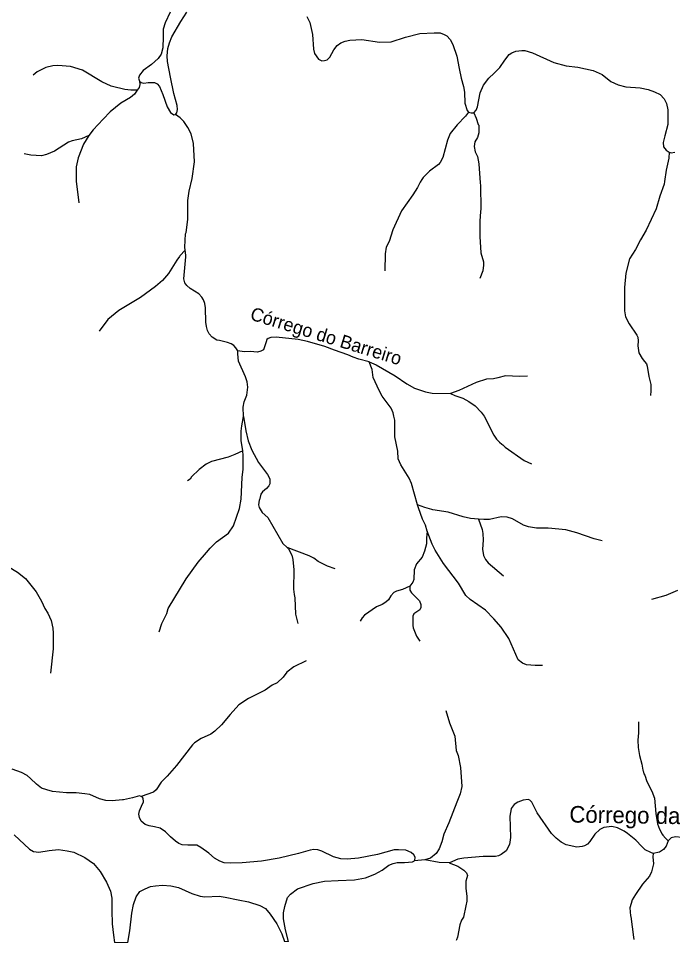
# Model space of a CAD drawing. Extents: x 396 to 422.2, y 7649.8 to 7677.6.
# Drawn here: x 405.17 to 409.11, y 7649.88 to 7655.45 of the extents above; entities that cross this region are included whole.
import ezdxf
from ezdxf.enums import TextEntityAlignment as Align

# ---------------------------------------------------------------- set-up
doc = ezdxf.new("R2010")
doc.units = 0
doc.header["$LTSCALE"] = 0.032
doc.linetypes.add('SHORT_DASHED', pattern=[2.7, 1.5, -1.2])
for name, color, linetype, lineweight in [('2', 7, 'Continuous', 25), ('62', 7, 'SHORT_DASHED', 13), ('7', 7, 'Continuous', 25)]:
    doc.layers.add(name, color=color, linetype=linetype, lineweight=lineweight)
doc.layers.add('61', color=7, linetype='Continuous')

msp = doc.modelspace()

# ---------------------------------------------------------------- linework, layer by layer
at = {"layer": '2'}
for points in [[(406.0836, 7655.4872), (406.0541, 7655.4214), (406.0423, 7655.384), (406.0423, 7655.3368), (406.0394, 7655.2719), (406.0305, 7655.2336), (406.0128, 7655.207), (405.9715, 7655.1716), (405.9223, 7655.1342), (405.8987, 7655.1067), (405.8938, 7655.088), (405.8995, 7655.0714)], [(406.1173, 7654.869), (406.1249, 7654.8796), (406.1288, 7654.8992), (406.1259, 7654.9238), (406.1072, 7654.9966), (406.0875, 7655.0949), (406.0679, 7655.1883), (406.0669, 7655.2227), (406.0708, 7655.268), (406.0797, 7655.3014), (406.0944, 7655.3368), (406.1485, 7655.4302), (406.1849, 7655.4853)], [(406.9086, 7655.4597), (406.9263, 7655.4233), (406.942, 7655.3525), (406.9489, 7655.2631), (406.9538, 7655.2375), (406.9794, 7655.2031), (406.9981, 7655.1932), (407.0158, 7655.1942), (407.0305, 7655.2001), (407.0462, 7655.2159), (407.0708, 7655.2601), (407.0905, 7655.2857), (407.1131, 7655.3024), (407.1387, 7655.3112), (407.1682, 7655.3181), (407.239, 7655.3211), (407.3462, 7655.3053), (407.416, 7655.3073), (407.5025, 7655.3348), (407.589, 7655.3575), (407.6756, 7655.3624), (407.7129, 7655.3624), (407.7365, 7655.3525), (407.7523, 7655.3437), (407.7719, 7655.3221), (407.7886, 7655.2906), (407.8122, 7655.2208), (407.827, 7655.147), (407.8378, 7655.089), (407.8526, 7655.0389), (407.8594, 7655.0054), (407.8614, 7654.9376), (407.8742, 7654.8933), (407.8833, 7654.8837)], [(407.9149, 7654.8798), (407.9292, 7654.8953), (407.9381, 7654.916), (407.946, 7654.9582), (407.9538, 7655.0005), (407.9735, 7655.0467), (408.0059, 7655.089), (408.0374, 7655.1185), (408.0708, 7655.1539), (408.1013, 7655.1972), (408.1289, 7655.2306), (408.1436, 7655.2414), (408.1692, 7655.2513), (408.2046, 7655.2562), (408.2223, 7655.2562), (408.2695, 7655.2404), (408.3983, 7655.1834), (408.471, 7655.1637), (408.5428, 7655.1559), (408.6343, 7655.1352), (408.6884, 7655.1116), (408.7415, 7655.0684), (408.7847, 7655.0477), (408.8309, 7655.0369), (408.9175, 7655.03), (408.9656, 7655.0212), (409.004, 7655.0074), (409.0374, 7654.9897), (409.062, 7654.9641), (409.0758, 7654.9366), (409.0836, 7654.8973), (409.0836, 7654.8688), (409.0846, 7654.8088), (409.0669, 7654.7419), (409.0561, 7654.7006), (409.0591, 7654.676), (409.0738, 7654.6554), (409.0918, 7654.6429)], [(405.8995, 7655.0714), (405.9096, 7655.0634), (405.9263, 7655.0585), (405.9528, 7655.0634), (405.9892, 7655.0634), (406.0059, 7655.0546), (406.0207, 7655.0389), (406.0394, 7654.9907), (406.0659, 7654.916), (406.0856, 7654.8825), (406.1072, 7654.8688), (406.1173, 7654.869)], [(407.8833, 7654.8837), (407.8988, 7654.8796), (407.9149, 7654.8798)], [(409.0918, 7654.6429), (409.1053, 7654.6387), (409.1259, 7654.6426)], [(405.9096, 7650.7626), (405.8999, 7650.7654), (405.8568, 7650.7537), (405.8033, 7650.7421), (405.7966, 7650.7415), (405.7346, 7650.7363), (405.6974, 7650.7386), (405.6589, 7650.7491), (405.5996, 7650.7747), (405.5705, 7650.7793), (405.5181, 7650.784), (405.4588, 7650.784), (405.3761, 7650.7921), (405.3412, 7650.8026), (405.3086, 7650.8131), (405.2783, 7650.8364), (405.2423, 7650.8713), (405.2225, 7650.8887), (405.1876, 7650.9074), (405.1329, 7650.9271)], [(407.5579, 7650.3752), (407.562, 7650.3906), (407.5608, 7650.3976), (407.5527, 7650.4115), (407.5375, 7650.4243), (407.5049, 7650.4383), (407.4607, 7650.4418), (407.4339, 7650.4418), (407.3338, 7650.4138), (407.2198, 7650.3906), (407.1523, 7650.3848), (407.1127, 7650.3871), (407.0696, 7650.3987), (406.9986, 7650.4336), (406.9753, 7650.4418), (406.9509, 7650.4429), (406.9288, 7650.4395), (406.8578, 7650.4197), (406.7414, 7650.3917), (406.6343, 7650.3731), (406.5191, 7650.3638), (406.4458, 7650.3615), (406.4097, 7650.3638), (406.3841, 7650.3731), (406.3526, 7650.3917), (406.3177, 7650.4208), (406.27, 7650.4558), (406.2456, 7650.4686), (406.2235, 7650.4697), (406.1909, 7650.4697), (406.1559, 7650.472), (406.1373, 7650.479), (406.1164, 7650.493), (406.0873, 7650.5198), (406.0558, 7650.55), (406.0233, 7650.5721), (405.9907, 7650.5791), (405.9581, 7650.5861), (405.9336, 7650.5943), (405.9104, 7650.614), (405.8987, 7650.635), (405.8964, 7650.6559), (405.8987, 7650.6769), (405.9127, 7650.7048), (405.9232, 7650.7293), (405.922, 7650.7514), (405.9162, 7650.7607), (405.9096, 7650.7626)], [(405.1437, 7650.5315), (405.2367, 7650.4443), (405.2609, 7650.4317), (405.2919, 7650.4279), (405.3558, 7650.4375), (405.412, 7650.4424), (405.4643, 7650.4346), (405.5031, 7650.4269), (405.5709, 7650.3949), (405.6232, 7650.3581), (405.6629, 7650.3107), (405.7007, 7650.2467), (405.7249, 7650.1915), (405.7327, 7650.1508), (405.7327, 7650.0753), (405.7346, 7649.9958), (405.7423, 7649.928), (405.7491, 7649.8829)], [(406.798, 7649.8889), (406.7788, 7649.9584), (406.768, 7650.0253), (406.768, 7650.0615), (406.7752, 7650.0994), (406.7926, 7650.1543), (406.8101, 7650.1741), (406.8531, 7650.2055), (406.9474, 7650.2381), (407.0149, 7650.2532), (407.0976, 7650.2567), (407.1965, 7650.2602), (407.2617, 7650.2719), (407.3187, 7650.294), (407.3629, 7650.3196), (407.4025, 7650.3487), (407.4293, 7650.358), (407.4526, 7650.365), (407.498, 7650.365), (407.5457, 7650.3685), (407.5579, 7650.3752)], [(405.83, 7649.8834), (405.8412, 7649.9542), (405.8528, 7650.0588), (405.8634, 7650.1111), (405.8789, 7650.1586), (405.9022, 7650.1896), (405.9341, 7650.206), (405.9651, 7650.2206), (405.9971, 7650.2244), (406.0378, 7650.2293), (406.0882, 7650.2235), (406.1347, 7650.2138), (406.216, 7650.1779), (406.2645, 7650.1624), (406.2935, 7650.1586), (406.3807, 7650.1624), (406.4156, 7650.1557), (406.494, 7650.1402), (406.557, 7650.1276), (406.6258, 7650.1053), (406.6597, 7650.0869), (406.6878, 7650.0539), (406.7285, 7649.9949), (406.7575, 7649.9358), (406.7743, 7649.8888)]]:
    msp.add_lwpolyline(points, dxfattribs=at)
at = {"layer": '62'}
msp.add_line((406.7743, 7649.8888), (406.798, 7649.8889), dxfattribs=at)
msp.add_lwpolyline([(405.7491, 7649.8829), (405.7669, 7649.883), (405.83, 7649.8834)], dxfattribs=at)
at = {"layer": '7'}
msp.add_line((407.6193, 7650.3803), (407.5579, 7650.3752), dxfattribs=at)
for points in [[(405.8859, 7655.0166), (405.8483, 7655.0167), (405.8107, 7655.0205), (405.7376, 7655.0385), (405.7283, 7655.0408), (405.6736, 7655.0665), (405.5571, 7655.1377), (405.4842, 7655.1592), (405.4065, 7655.1657), (405.3781, 7655.1633), (405.3353, 7655.1526), (405.2825, 7655.1274), (405.2594, 7655.106)], [(405.8995, 7655.0714), (405.9011, 7655.0509), (405.8969, 7655.0319), (405.8859, 7655.0166)], [(405.8859, 7655.0166), (405.8689, 7654.9929), (405.8458, 7654.9729), (405.7866, 7654.9372), (405.7234, 7654.8858), (405.6808, 7654.8408), (405.62, 7654.7766), (405.5945, 7654.7444)], [(406.1748, 7654.0525), (406.1725, 7654.0701), (406.1773, 7654.1517), (406.1805, 7654.1596), (406.1901, 7654.2366), (406.1909, 7654.3514), (406.1996, 7654.4085), (406.2178, 7654.4838), (406.2315, 7654.5843), (406.2258, 7654.6952), (406.2115, 7654.7526), (406.1912, 7654.7917), (406.1663, 7654.8278), (406.1445, 7654.8501), (406.1173, 7654.869)], [(407.8833, 7654.8837), (407.8658, 7654.8597), (407.8151, 7654.8074), (407.7715, 7654.7558), (407.7559, 7654.7163), (407.7275, 7654.6107), (407.7124, 7654.5811), (407.703, 7654.5695), (407.6469, 7654.5277), (407.6093, 7654.49), (407.6012, 7654.4782), (407.5908, 7654.463), (407.5746, 7654.4307), (407.5467, 7654.386), (407.4791, 7654.2891), (407.4274, 7654.1748), (407.4041, 7654.1042), (407.3863, 7654.0707), (407.3799, 7654.0307), (407.3783, 7653.9289)], [(407.9149, 7654.8798), (407.9296, 7654.8476), (407.9413, 7654.8096), (407.9445, 7654.8065), (407.9461, 7654.7586), (407.9365, 7654.7321), (407.9214, 7654.7046), (407.9173, 7654.6763), (407.9234, 7654.6454), (407.9363, 7654.6162), (407.946, 7654.5731), (407.9524, 7654.4579), (407.9556, 7654.4432), (407.9564, 7654.3023), (407.955, 7654.284), (407.9508, 7654.2294), (407.9517, 7654.1349), (407.9573, 7654.0365), (407.9732, 7653.9819), (407.9733, 7653.9621), (407.9684, 7653.928), (407.9517, 7653.8826)], [(405.5945, 7654.7444), (405.5491, 7654.7227), (405.4933, 7654.7104), (405.4722, 7654.7031), (405.3867, 7654.6489), (405.3392, 7654.6281), (405.3085, 7654.6211), (405.2451, 7654.6243), (405.2052, 7654.6331)], [(405.5945, 7654.7444), (405.5628, 7654.6913), (405.5301, 7654.6091), (405.517, 7654.5552), (405.5185, 7654.4687), (405.5345, 7654.3388)], [(409.0918, 7654.6429), (409.0912, 7654.6067), (409.0737, 7654.5354), (409.0648, 7654.4668), (409.0625, 7654.4495), (409.0372, 7654.3782), (409.0147, 7654.3012), (408.9546, 7654.1729), (408.9192, 7654.1149), (408.8897, 7654.0575), (408.853, 7654), (408.8314, 7653.914), (408.8235, 7653.8282), (408.8233, 7653.6874), (408.8299, 7653.6517), (408.8511, 7653.6093), (408.8983, 7653.5412), (408.903, 7653.5297), (408.9053, 7653.506), (408.9031, 7653.4763), (408.91, 7653.4343), (408.9297, 7653.3999), (408.9438, 7653.3825), (408.9558, 7653.3677), (408.9604, 7653.3542), (408.9693, 7653.2913), (408.9828, 7653.2442), (408.9828, 7653.2051), (408.9797, 7653.1776)], [(406.1748, 7654.0525), (406.1438, 7654.0193), (406.1404, 7654.0147), (406.1242, 7653.9928), (406.0736, 7653.9124), (406.039, 7653.8704), (405.9968, 7653.8344), (405.9056, 7653.7671), (405.7755, 7653.6899), (405.7081, 7653.6351), (405.6566, 7653.5652)], [(406.4915, 7653.4462), (406.48, 7653.4651), (406.4679, 7653.4792), (406.4517, 7653.4891), (406.4294, 7653.4975), (406.3821, 7653.5078), (406.3659, 7653.5113), (406.3373, 7653.5296), (406.3204, 7653.5489), (406.3099, 7653.5681), (406.3026, 7653.5924), (406.2993, 7653.6182), (406.2984, 7653.7054), (406.2941, 7653.7314), (406.2851, 7653.7546), (406.2755, 7653.77), (406.2572, 7653.789), (406.2059, 7653.8227), (406.1849, 7653.8398), (406.173, 7653.8567), (406.1669, 7653.8798), (406.178, 7654.0127), (406.1788, 7654.0221), (406.1748, 7654.0525)], [(407.2837, 7653.3811), (407.2218, 7653.3965), (407.1877, 7653.4083), (407.1558, 7653.4234), (407.0744, 7653.45), (407.0166, 7653.4733), (406.9133, 7653.5023), (406.8559, 7653.5144), (406.7235, 7653.5292), (406.6908, 7653.5276), (406.675, 7653.5212), (406.6672, 7653.5149), (406.6626, 7653.5001), (406.6475, 7653.4521), (406.6321, 7653.4441), (406.6115, 7653.4384), (406.5668, 7653.4431), (406.5309, 7653.4408), (406.4915, 7653.4462)], [(406.527, 7653.051), (406.5253, 7653.1073), (406.5313, 7653.1402), (406.5464, 7653.1799), (406.5536, 7653.2282), (406.5496, 7653.2597), (406.5396, 7653.2909), (406.4964, 7653.3841), (406.493, 7653.429), (406.4915, 7653.4462)], [(407.575, 7652.519), (407.54, 7652.6475), (407.5251, 7652.6804), (407.4746, 7652.7608), (407.4598, 7652.7952), (407.4563, 7652.8425), (407.4389, 7652.9276), (407.4388, 7653.0284), (407.4335, 7653.0524), (407.4291, 7653.0722), (407.4169, 7653.1009), (407.363, 7653.173), (407.3439, 7653.207), (407.309, 7653.2865), (407.3017, 7653.3343), (407.2837, 7653.3811)], [(407.2837, 7653.3811), (407.3261, 7653.3619), (407.4413, 7653.2961), (407.5106, 7653.2485), (407.5582, 7653.2224), (407.623, 7653.1996), (407.6646, 7653.1912), (407.7748, 7653.1901)], [(408.2388, 7653.2933), (408.1909, 7653.2916), (408.106, 7653.2955), (408.0599, 7653.2844), (408.0338, 7653.2781), (407.9911, 7653.2749), (407.9282, 7653.2556), (407.8252, 7653.208), (407.7748, 7653.1901)], [(407.7748, 7653.1901), (407.8, 7653.1781), (407.8491, 7653.1615), (407.8853, 7653.1418), (407.9224, 7653.1159), (407.9593, 7653.0772), (407.9764, 7653.0539), (408.0366, 7652.939), (408.0527, 7652.9154), (408.0706, 7652.8959), (408.0842, 7652.8842), (408.0889, 7652.8802), (408.1048, 7652.8666), (408.2188, 7652.7859), (408.2628, 7652.7661)], [(406.522, 7652.8444), (406.5123, 7652.9061), (406.5116, 7652.9622), (406.5157, 7652.9956), (406.527, 7653.051)], [(406.527, 7653.051), (406.5409, 7652.9638), (406.5539, 7652.9049), (406.5775, 7652.8482), (406.6175, 7652.7745), (406.6711, 7652.7018), (406.6844, 7652.6759), (406.6844, 7652.6445), (406.6795, 7652.6342), (406.6653, 7652.617), (406.6413, 7652.5977), (406.6316, 7652.5827), (406.6238, 7652.5495), (406.6207, 7652.5471), (406.6176, 7652.518), (406.6207, 7652.5024), (406.6395, 7652.4738), (406.6726, 7652.4424), (406.7638, 7652.2861), (406.79, 7652.2612)], [(406.0187, 7651.7544), (406.0351, 7651.8046), (406.0639, 7651.8653), (406.0725, 7651.8941), (406.1806, 7652.0733), (406.2527, 7652.1733), (406.3026, 7652.2319), (406.3253, 7652.2586), (406.3641, 7652.2971), (406.4358, 7652.3476), (406.4657, 7652.3917), (406.5028, 7652.4964), (406.5122, 7652.554), (406.5194, 7652.6846), (406.525, 7652.7338), (406.5249, 7652.8168), (406.522, 7652.8444)], [(406.522, 7652.8444), (406.4752, 7652.8217), (406.4347, 7652.8062), (406.3347, 7652.7792), (406.3014, 7652.7631), (406.2597, 7652.7311), (406.2137, 7652.6869), (406.2043, 7652.6744), (406.1893, 7652.6632)], [(407.6347, 7652.3604), (407.624, 7652.3958), (407.6059, 7652.4321), (407.6054, 7652.4336), (407.581, 7652.5006), (407.575, 7652.519)], [(407.9432, 7652.4331), (407.8944, 7652.4374), (407.8501, 7652.4475), (407.7606, 7652.4746), (407.6687, 7652.4892), (407.6615, 7652.4903), (407.6191, 7652.5036), (407.575, 7652.519)], [(408.6886, 7652.302), (408.6399, 7652.3146), (408.535, 7652.3504), (408.4705, 7652.3681), (408.3628, 7652.3792), (408.2932, 7652.3794), (408.2453, 7652.3861), (408.2144, 7652.3958), (408.1486, 7652.4342), (408.1151, 7652.4446), (408.0797, 7652.4462), (408.0103, 7652.4304), (407.9744, 7652.4304), (407.9432, 7652.4331)], [(407.9432, 7652.4331), (407.9649, 7652.3709), (407.9701, 7652.3454), (407.9716, 7652.3068), (407.9669, 7652.2529), (407.9732, 7652.2146), (407.9847, 7652.1904), (408.0012, 7652.1687), (408.0929, 7652.0914)], [(407.6347, 7652.3604), (407.6303, 7652.3181), (407.6301, 7652.2844), (407.6182, 7652.2395), (407.6027, 7652.2047), (407.5696, 7652.1634), (407.5554, 7652.1272), (407.5537, 7652.0699), (407.5473, 7652.0539), (407.5299, 7652.0284)], [(408.3299, 7651.5519), (408.2852, 7651.551), (408.2329, 7651.5563), (408.2077, 7651.5651), (408.1823, 7651.5857), (408.1251, 7651.7135), (408.0798, 7651.7814), (408.0365, 7651.8317), (407.9854, 7651.8838), (407.8935, 7651.9495), (407.8676, 7651.9735), (407.8236, 7652.0465), (407.7314, 7652.165), (407.6812, 7652.2455), (407.6629, 7652.2816), (407.6347, 7652.3604)], [(406.79, 7652.2612), (406.7972, 7652.2543), (406.8184, 7652.2149), (406.8247, 7652.1901), (406.8296, 7652.1268), (406.828, 7652.0108), (406.8323, 7651.9795), (406.8352, 7651.9585), (406.8391, 7651.8597), (406.8536, 7651.8043)], [(407.0793, 7652.1329), (407.0324, 7652.1486), (406.9937, 7652.1687), (406.9768, 7652.1775), (406.9499, 7652.197), (406.9216, 7652.2116), (406.79, 7652.2612)], [(404.4661, 7652.167), (404.5329, 7652.1834), (404.5532, 7652.1866), (404.7226, 7652.2136), (404.8333, 7652.2205), (404.8366, 7652.2157), (404.9564, 7652.1982), (404.9738, 7652.1957), (405.0372, 7652.1805), (405.1085, 7652.1476), (405.1646, 7652.1142), (405.2116, 7652.0744), (405.2764, 7651.9954), (405.3081, 7651.9387), (405.3286, 7651.8946), (405.3478, 7651.8656), (405.367, 7651.8223), (405.3764, 7651.7771), (405.3797, 7651.7452), (405.3797, 7651.7387), (405.3798, 7651.6522), (405.3623, 7651.5061)], [(407.5299, 7652.0284), (407.5298, 7652.0283), (407.4854, 7652.0091), (407.4487, 7652), (407.4331, 7651.9914), (407.4143, 7651.9711), (407.4004, 7651.9476), (407.3847, 7651.9334), (407.3617, 7651.9196), (407.3283, 7651.9049), (407.2553, 7651.855), (407.2423, 7651.8394), (407.2308, 7651.8187)], [(407.5299, 7652.0284), (407.5299, 7652.0056), (407.54, 7651.9895), (407.5875, 7651.94), (407.5959, 7651.9186), (407.5954, 7651.9001), (407.5888, 7651.8873), (407.5541, 7651.8635), (407.5473, 7651.8489), (407.5465, 7651.7917), (407.5488, 7651.7786), (407.5703, 7651.7288), (407.5889, 7651.6975)], [(408.9882, 7651.9509), (409.0744, 7651.9752), (409.1454, 7652.0047)], [(406.9038, 7651.5794), (406.8305, 7651.5426), (406.7881, 7651.5107), (406.7656, 7651.4802), (406.7294, 7651.4479), (406.6996, 7651.4334), (406.658, 7651.4035), (406.5563, 7651.3522), (406.4984, 7651.3152), (406.4469, 7651.2559), (406.3934, 7651.1943), (406.3538, 7651.1561), (406.33, 7651.1382), (406.2717, 7651.1113), (406.2306, 7651.0854), (406.219, 7651.074), (406.122, 7650.9492), (406.067, 7650.8853), (406.0294, 7650.8486), (405.9999, 7650.8024), (405.9843, 7650.788), (405.9096, 7650.7626)], [(407.746, 7651.2812), (407.768, 7651.2061), (407.8011, 7651.1249), (407.8087, 7651.0391), (407.8201, 7651.0088), (407.8352, 7650.9378), (407.8423, 7650.8218), (407.8327, 7650.7791), (407.8129, 7650.7286), (407.7641, 7650.6037), (407.7343, 7650.5354), (407.7226, 7650.4885), (407.707, 7650.4464), (407.6874, 7650.4188), (407.653, 7650.3917), (407.6193, 7650.3803)], [(408.9079, 7651.2126), (408.9086, 7651.146), (408.9031, 7651.1008), (408.9063, 7651.0567), (408.9136, 7651.0093), (408.9285, 7650.9572), (408.9332, 7650.9205), (408.9365, 7650.9179), (408.9399, 7650.899), (408.9459, 7650.8901), (408.9576, 7650.8521), (408.9886, 7650.7951), (409.005, 7650.7527), (409.0125, 7650.66), (409.023, 7650.5969), (409.0349, 7650.565), (409.05, 7650.5352), (409.0552, 7650.5288), (409.0697, 7650.5108), (409.0875, 7650.4962)], [(408.2968, 7650.6649), (408.265, 7650.7284), (408.2534, 7650.7402), (408.2422, 7650.7444), (408.2124, 7650.7411), (408.1798, 7650.7281), (408.1578, 7650.7143), (408.1401, 7650.6899), (408.1392, 7650.6887), (408.1328, 7650.6447), (408.1359, 7650.5159), (408.1296, 7650.4733), (408.1091, 7650.4357), (408.0803, 7650.4135), (408.0644, 7650.4056), (408.0456, 7650.4015), (407.9708, 7650.4014), (407.8539, 7650.3905), (407.8196, 7650.3844), (407.7676, 7650.3638), (407.7673, 7650.3638)], [(408.997, 7650.4195), (408.9811, 7650.4242), (408.9472, 7650.4418), (408.9281, 7650.4615), (408.8917, 7650.499), (408.8423, 7650.5405), (408.8222, 7650.5539), (408.7806, 7650.5736), (408.746, 7650.5808), (408.6981, 7650.5749), (408.675, 7650.5638), (408.6442, 7650.5355), (408.6152, 7650.4919), (408.6003, 7650.4751), (408.582, 7650.4646), (408.5688, 7650.4606), (408.5359, 7650.4581), (408.4721, 7650.471), (408.442, 7650.4871), (408.4105, 7650.5113), (408.3829, 7650.5397), (408.2968, 7650.6649)], [(409.467, 7650.5278), (409.4565, 7650.5156), (409.4486, 7650.4728), (409.4281, 7650.4606), (409.4087, 7650.4549), (409.313, 7650.4636), (409.2542, 7650.4754), (409.1682, 7650.5153), (409.1311, 7650.5186), (409.1044, 7650.5124), (409.0875, 7650.4962)], [(409.0875, 7650.4962), (409.0752, 7650.4636), (409.0579, 7650.4434), (409.0348, 7650.4273), (408.997, 7650.4195)], [(408.997, 7650.4195), (408.9949, 7650.3995), (408.9972, 7650.3568), (408.9856, 7650.3091), (408.973, 7650.2824), (408.9326, 7650.2348), (408.8887, 7650.1718), (408.8702, 7650.1396), (408.8633, 7650.1177), (408.8553, 7650.0924), (408.8585, 7650.043), (408.8616, 7650.0398), (408.8784, 7649.9159), (408.8805, 7649.9006)], [(407.7673, 7650.3638), (407.7054, 7650.3649), (407.6193, 7650.3803)], [(407.7673, 7650.3638), (407.8182, 7650.3418), (407.8554, 7650.3191), (407.8709, 7650.3019), (407.8759, 7650.2871), (407.8735, 7650.2721), (407.8664, 7650.2515), (407.8663, 7650.2088), (407.8727, 7650.163), (407.8726, 7650.1312), (407.8669, 7650.1042), (407.8526, 7650.0362), (407.8407, 7650.0183), (407.8297, 7649.9899), (407.8168, 7649.9147), (407.8098, 7649.8983), (407.8082, 7649.8947)]]:
    msp.add_lwpolyline(points, dxfattribs=at)

# ---------------------------------------------------------------- texts
at = {"layer": '61'}
for s, height, rotation, p in [('Córrego do Barreiro', 0.08, 342.957, (407.0132, 7653.4973)), ('Córrego da Fortaleza', 0.1, 359.165, (409.122, 7650.5965))]:
    msp.add_text(s, height=height, rotation=rotation, dxfattribs=at).set_placement(p, align=Align.CENTER)

doc.saveas('drawing.dxf')
